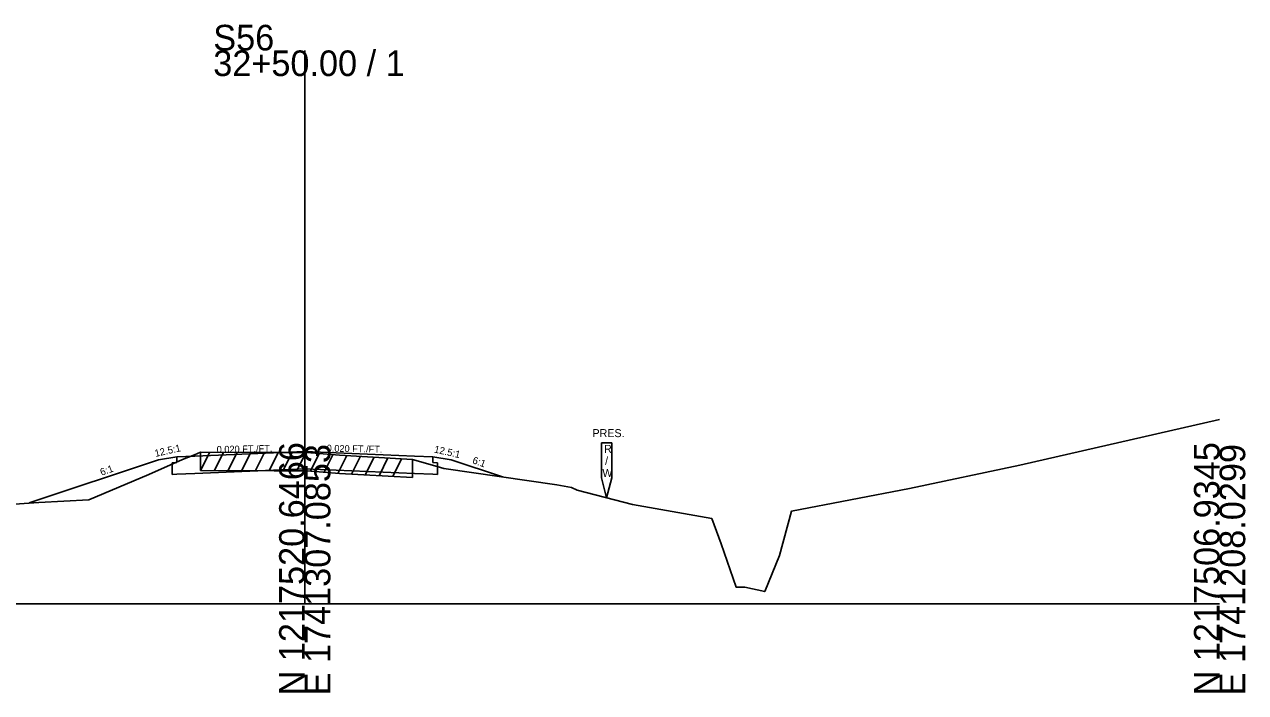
# Model space of a CAD drawing. Extents: x -26 to 1203, y -10 to 19541.
# Drawn here: x 69.4 to 202.8, y 7490.3 to 7563.4 of the extents above; entities that cross this region are included whole.
import ezdxf

# ---------------------------------------------------------------- set-up
doc = ezdxf.new("R2010")
doc.units = 0
for name, color, linetype in [('RD_GPK_XS_Cell', 7, 'Continuous'), ('RD_XS_Base', 7, 'Continuous'), ('RD_XS_EarthShd', 7, 'Continuous'), ('RD_XS_ExGround', 7, 'Continuous'), ('RD_XS_ExPaveRet', 7, 'Continuous'), ('RD_XS_ExRW', 7, 'Continuous'), ('RD_XS_Pave', 7, 'Continuous'), ('RD_XS_TX_Elev_EX', 7, 'Continuous'), ('RD_XS_TX_Slope', 7, 'Continuous')]:
    doc.layers.add(name, color=color, linetype=linetype)

msp = doc.modelspace()

# ---------------------------------------------------------------- linework, layer by layer
at = {"layer": 'RD_GPK_XS_Cell'}
for p, q in [((100, 7500), (100, 7560.52)), ((0, 7500), (100, 7500)), ((100, 7500), (200, 7500))]:
    msp.add_line(p, q, dxfattribs=at)
at = {"layer": 'RD_XS_Base'}
for p, q in [((86, 7515.45), (85.5, 7515.43)), ((85.5, 7514.16), (85.5, 7515.43)), ((86, 7515.45), (86, 7516.09)), ((114, 7515.45), (114, 7516.09)), ((114, 7515.45), (114.5, 7515.43)), ((114.5, 7514.16), (114.5, 7515.43)), ((86, 7514.18), (85.5, 7514.16)), ((86, 7514.18), (88, 7514.26)), ((88, 7514.26), (100, 7514.76)), ((112, 7514.26), (100, 7514.76)), ((114, 7514.18), (112, 7514.26)), ((114, 7514.18), (114.5, 7514.16))]:
    msp.add_line(p, q, dxfattribs=at)
at = {"layer": 'RD_XS_EarthShd'}
for p, q in [((84, 7515.75), (69.86, 7511.04)), ((86, 7516.09), (84, 7515.75)), ((114, 7516.09), (116, 7515.75)), ((116, 7515.75), (121.6, 7513.89))]:
    msp.add_line(p, q, dxfattribs=at)
at = {"layer": 'RD_XS_ExGround'}
msp.add_lwpolyline([(22.53, 7507.76), (70.92, 7511.09), (76.41, 7511.38), (82.97, 7514.14), (86.63, 7515.79), (87.94, 7516.32), (88.62, 7516.6), (96.65, 7516.57), (100.23, 7516.55), (103.81, 7516.27), (111.76, 7515.81), (114.47, 7515.03), (115.22, 7514.81), (127.54, 7513.03), (129.14, 7512.72), (129.76, 7512.43), (135.84, 7510.86), (144.49, 7509.34), (145.52, 7506.58), (147.14, 7501.85), (148.11, 7501.83), (150.28, 7501.35), (151.88, 7505.3), (153.21, 7510.15), (166.12, 7512.63), (178.15, 7515.16), (200, 7520.17)], dxfattribs=at)
at = {"layer": 'RD_XS_ExPaveRet'}
for p, q in [((88.62, 7514.6), (89.61, 7516.6)), ((88.62, 7514.6), (88.62, 7516.6)), ((90.12, 7514.6), (91.11, 7516.59)), ((91.62, 7514.59), (92.61, 7516.59)), ((93.12, 7514.58), (94.11, 7516.58)), ((94.62, 7514.58), (95.61, 7516.57)), ((96.12, 7514.57), (97.11, 7516.57)), ((97.62, 7514.56), (98.61, 7516.56)), ((99.12, 7514.56), (100.11, 7516.55)), ((100.62, 7514.52), (101.58, 7516.44)), ((102.12, 7514.4), (103.08, 7516.32)), ((103.62, 7514.28), (104.59, 7516.22)), ((105.12, 7514.19), (106.09, 7516.14)), ((106.62, 7514.11), (107.59, 7516.05)), ((108.12, 7514.02), (109.09, 7515.97)), ((109.62, 7513.94), (110.59, 7515.88)), ((111.76, 7515.81), (111.76, 7513.81)), ((88.62, 7514.6), (96.65, 7514.57)), ((96.65, 7514.57), (100.23, 7514.55)), ((100.23, 7514.55), (103.81, 7514.27)), ((103.81, 7514.27), (111.76, 7513.81))]:
    msp.add_line(p, q, dxfattribs=at)
at = {"layer": 'RD_XS_ExRW'}
msp.add_lwpolyline([(132.45, 7517.61), (133.55, 7517.61), (133.55, 7513.78), (133, 7511.6), (132.45, 7513.78)], close=True, dxfattribs=at)
at = {"layer": 'RD_XS_Pave'}
for p, q in [((88, 7516.17), (100, 7516.67)), ((112, 7516.17), (100, 7516.67)), ((86, 7516.09), (88, 7516.17)), ((114, 7516.09), (112, 7516.17))]:
    msp.add_line(p, q, dxfattribs=at)

# ---------------------------------------------------------------- texts
at = {"layer": 'RD_GPK_XS_Cell'}
for s, p in [('S56', (90, 7560.52)), ('32+50.00 / 1', (90, 7557.72))]:
    msp.add_text(s, height=2.8, dxfattribs=at).set_placement(p)
for s, p in [('N 1217520.6466', (100, 7490)), ('E 1741307.0853', (102.8, 7490)), ('N 1217506.9345', (200, 7490)), ('E 1741208.0299', (202.8, 7490))]:
    msp.add_text(s, height=2.8, rotation=90, dxfattribs=at).set_placement(p)
at = {"layer": 'RD_XS_ExRW'}
for s, p in [('PRES.', (131.45, 7518.24)), ('R', (132.71, 7516.52)), ('/', (132.83, 7515.21)), ('W', (132.53, 7513.89))]:
    msp.add_text(s, height=0.875, dxfattribs=at).set_placement(p)
at = {"layer": 'RD_XS_TX_Elev_EX'}
msp.add_text('846.28', height=0.1, rotation=90, dxfattribs=at).set_placement((100.1, 7516.55))
at = {"layer": 'RD_XS_TX_Slope'}
for s, height, rotation, p in [('12.5:1', 0.778, 12.7511, (83.69, 7516.07)), ('0.020 FT./FT.', 0.7518, 1.1916, (90.38, 7516.51)), ('0.020 FT./FT.', 0.7518, 358.8084, (102.39, 7516.66)), ('12.5:1', 0.778, 347.2489, (114.09, 7516.57)), ('6:1', 0.778, 19.3982, (77.79, 7514.01)), ('6:1', 0.778, 340.6018, (118.26, 7515.4))]:
    msp.add_text(s, height=height, rotation=rotation, dxfattribs=at).set_placement(p)

doc.saveas('drawing.dxf')
